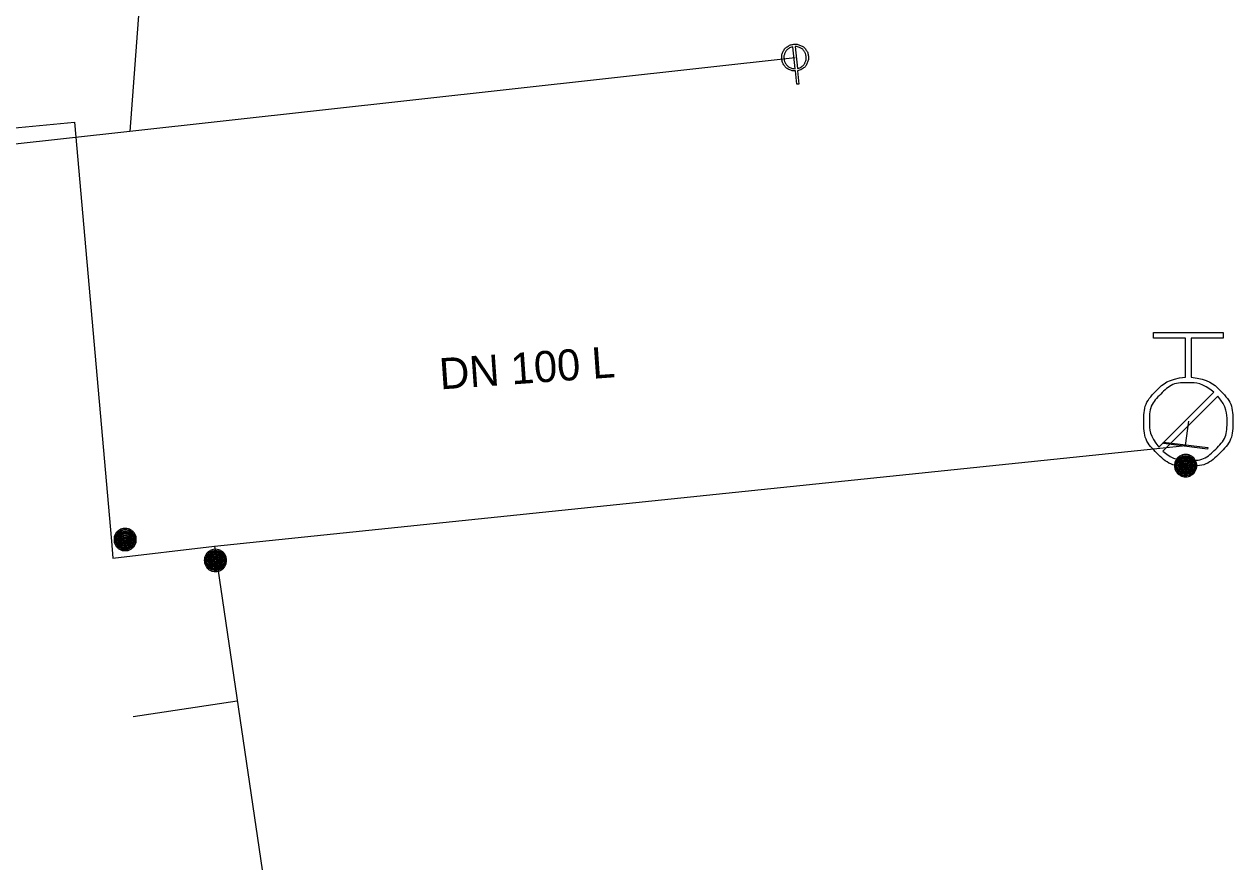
# Model space of a CAD drawing. Extents: x -818321 to -817653, y -1049725 to -1049329.
# Drawn here: x -817742.06 to -817714.89, y -1049399.87 to -1049380.87 of the extents above; entities that cross this region are included whole.
import ezdxf

# ---------------------------------------------------------------- set-up
doc = ezdxf.new("R2010")
doc.units = 0
doc.layers.add('Default', color=7, linetype='Continuous')
doc.layers.add('Level 0', color=7, linetype='Continuous')

msp = doc.modelspace()

# ---------------------------------------------------------------- linework, layer by layer
at = {"layer": 'Default'}
for points in [[(-817724.728, -1049381.869), (-817724.78, -1049381.375)], [(-817724.731, -1049381.37), (-817724.679, -1049381.864)], [(-817724.674, -1049381.915), (-817724.642, -1049382.214), (-817724.691, -1049382.219), (-817724.723, -1049381.92)], [(-817715.952, -1049388.805), (-817715.952, -1049387.926), (-817716.67, -1049387.926), (-817716.67, -1049387.801), (-817715.108, -1049387.801), (-817715.108, -1049387.926), (-817715.827, -1049387.926), (-817715.827, -1049388.805)], [(-817716.549, -1049390.374), (-817715.317, -1049389.139)], [(-817715.227, -1049389.229), (-817716.461, -1049390.464)], [(-817716.444, -1049390.263), (-817715.452, -1049390.385), (-817715.456, -1049390.416), (-817716.448, -1049390.294), (-817716.444, -1049390.263)]]:
    msp.add_lwpolyline(points, dxfattribs=at)
for points in [[(-817724.723, -1049381.92), (-817724.785, -1049381.923), (-817724.851, -1049381.894), (-817724.926, -1049381.863), (-817724.973, -1049381.796), (-817725.02, -1049381.729), (-817725.028, -1049381.651), (-817725.036, -1049381.573), (-817725.003, -1049381.497), (-817724.971, -1049381.421), (-817724.904, -1049381.375), (-817724.837, -1049381.329), (-817724.761, -1049381.321), (-817724.686, -1049381.314), (-817724.61, -1049381.345), (-817724.535, -1049381.375), (-817724.487, -1049381.443), (-817724.439, -1049381.51), (-817724.431, -1049381.588), (-817724.423, -1049381.666), (-817724.455, -1049381.741), (-817724.487, -1049381.816), (-817724.554, -1049381.863), (-817724.612, -1049381.904), (-817724.674, -1049381.915)], [(-817724.78, -1049381.375), (-817724.827, -1049381.384), (-817724.875, -1049381.417), (-817724.931, -1049381.455), (-817724.958, -1049381.518), (-817724.985, -1049381.581), (-817724.978, -1049381.646), (-817724.972, -1049381.711), (-817724.933, -1049381.766), (-817724.894, -1049381.821), (-817724.831, -1049381.848), (-817724.777, -1049381.871), (-817724.728, -1049381.869)], [(-817724.679, -1049381.864), (-817724.631, -1049381.856), (-817724.582, -1049381.822), (-817724.527, -1049381.783), (-817724.5, -1049381.721), (-817724.474, -1049381.658), (-817724.481, -1049381.594), (-817724.488, -1049381.529), (-817724.527, -1049381.473), (-817724.567, -1049381.417), (-817724.63, -1049381.391), (-817724.683, -1049381.369), (-817724.731, -1049381.37)], [(-817715.827, -1049388.805), (-817715.438, -1049388.835), (-817715.18, -1049389.094), (-817714.889, -1049389.387), (-817714.889, -1049389.803), (-817714.889, -1049390.217), (-817715.182, -1049390.509), (-817715.475, -1049390.801), (-817715.891, -1049390.801), (-817716.303, -1049390.801), (-817716.596, -1049390.509), (-817716.889, -1049390.217), (-817716.889, -1049389.803), (-817716.889, -1049389.387), (-817716.598, -1049389.094), (-817716.34, -1049388.833), (-817715.952, -1049388.805)], [(-817715.317, -1049389.139), (-817715.559, -1049388.926), (-817715.891, -1049388.926), (-817716.254, -1049388.926), (-817716.509, -1049389.181), (-817716.764, -1049389.436), (-817716.764, -1049389.8), (-817716.764, -1049390.132), (-817716.549, -1049390.374)], [(-817716.461, -1049390.464), (-817716.221, -1049390.673), (-817715.891, -1049390.676), (-817715.53, -1049390.673), (-817715.274, -1049390.418), (-817715.018, -1049390.163), (-817715.018, -1049389.8), (-817715.018, -1049389.469), (-817715.227, -1049389.229)], [(-817715.95, -1049390.54), (-817715.887, -1049390.54), (-817715.827, -1049390.572), (-817715.767, -1049390.605), (-817715.734, -1049390.665), (-817715.7, -1049390.725), (-817715.7, -1049390.79), (-817715.7, -1049390.855), (-817715.733, -1049390.915), (-817715.766, -1049390.974), (-817715.825, -1049391.007), (-817715.885, -1049391.04), (-817715.95, -1049391.04), (-817716.015, -1049391.04), (-817716.074, -1049391.007), (-817716.134, -1049390.974), (-817716.167, -1049390.915), (-817716.2, -1049390.855), (-817716.2, -1049390.79), (-817716.2, -1049390.725), (-817716.166, -1049390.665), (-817716.133, -1049390.605), (-817716.073, -1049390.572), (-817716.013, -1049390.54), (-817715.95, -1049390.54)], [(-817715.95, -1049390.564), (-817716.007, -1049390.564), (-817716.061, -1049390.593), (-817716.116, -1049390.622), (-817716.146, -1049390.677), (-817716.176, -1049390.731), (-817716.176, -1049390.79), (-817716.176, -1049390.849), (-817716.147, -1049390.903), (-817716.117, -1049390.957), (-817716.063, -1049390.987), (-817716.009, -1049391.017), (-817715.95, -1049391.017), (-817715.891, -1049391.017), (-817715.837, -1049390.987), (-817715.783, -1049390.957), (-817715.753, -1049390.903), (-817715.723, -1049390.849), (-817715.723, -1049390.79), (-817715.723, -1049390.731), (-817715.754, -1049390.677), (-817715.785, -1049390.622), (-817715.839, -1049390.593), (-817715.893, -1049390.564), (-817715.95, -1049390.564)], [(-817715.95, -1049390.581), (-817715.897, -1049390.581), (-817715.847, -1049390.608), (-817715.797, -1049390.635), (-817715.769, -1049390.685), (-817715.74, -1049390.736), (-817715.74, -1049390.79), (-817715.74, -1049390.845), (-817715.768, -1049390.895), (-817715.795, -1049390.944), (-817715.845, -1049390.972), (-817715.895, -1049391), (-817715.95, -1049391), (-817716.004, -1049391), (-817716.054, -1049390.972), (-817716.104, -1049390.944), (-817716.132, -1049390.895), (-817716.159, -1049390.845), (-817716.159, -1049390.79), (-817716.159, -1049390.736), (-817716.131, -1049390.685), (-817716.103, -1049390.635), (-817716.053, -1049390.608), (-817716.003, -1049390.581), (-817715.95, -1049390.581)], [(-817715.95, -1049390.603), (-817716.028, -1049390.603), (-817716.083, -1049390.658), (-817716.137, -1049390.713), (-817716.137, -1049390.79), (-817716.137, -1049390.868), (-817716.082, -1049390.923), (-817716.027, -1049390.978), (-817715.95, -1049390.978), (-817715.872, -1049390.978), (-817715.817, -1049390.923), (-817715.762, -1049390.868), (-817715.762, -1049390.79), (-817715.762, -1049390.713), (-817715.817, -1049390.658), (-817715.871, -1049390.603), (-817715.95, -1049390.603)], [(-817715.95, -1049390.626), (-817715.882, -1049390.626), (-817715.834, -1049390.674), (-817715.786, -1049390.722), (-817715.786, -1049390.79), (-817715.786, -1049390.858), (-817715.834, -1049390.906), (-817715.882, -1049390.954), (-817715.95, -1049390.954), (-817716.019, -1049390.954), (-817716.067, -1049390.906), (-817716.114, -1049390.858), (-817716.114, -1049390.79), (-817716.114, -1049390.722), (-817716.067, -1049390.674), (-817716.019, -1049390.626), (-817715.95, -1049390.626)], [(-817715.95, -1049390.645), (-817716.01, -1049390.645), (-817716.052, -1049390.688), (-817716.095, -1049390.73), (-817716.095, -1049390.79), (-817716.095, -1049390.85), (-817716.052, -1049390.892), (-817716.01, -1049390.934), (-817715.95, -1049390.934), (-817715.891, -1049390.934), (-817715.848, -1049390.892), (-817715.806, -1049390.85), (-817715.806, -1049390.79), (-817715.806, -1049390.73), (-817715.848, -1049390.688), (-817715.89, -1049390.645), (-817715.95, -1049390.645)], [(-817715.95, -1049390.665), (-817715.898, -1049390.665), (-817715.861, -1049390.702), (-817715.825, -1049390.738), (-817715.825, -1049390.79), (-817715.825, -1049390.842), (-817715.861, -1049390.879), (-817715.898, -1049390.915), (-817715.95, -1049390.915), (-817716.002, -1049390.915), (-817716.038, -1049390.879), (-817716.075, -1049390.842), (-817716.075, -1049390.79), (-817716.075, -1049390.738), (-817716.039, -1049390.702), (-817716.002, -1049390.665), (-817715.95, -1049390.665)], [(-817715.95, -1049390.688), (-817715.992, -1049390.688), (-817716.022, -1049390.718), (-817716.052, -1049390.748), (-817716.052, -1049390.79), (-817716.052, -1049390.832), (-817716.022, -1049390.862), (-817715.992, -1049390.892), (-817715.95, -1049390.892), (-817715.908, -1049390.892), (-817715.878, -1049390.862), (-817715.849, -1049390.832), (-817715.849, -1049390.79), (-817715.849, -1049390.748), (-817715.878, -1049390.718), (-817715.908, -1049390.688), (-817715.95, -1049390.688)], [(-817715.95, -1049390.706), (-817715.915, -1049390.706), (-817715.89, -1049390.73), (-817715.866, -1049390.755), (-817715.866, -1049390.79), (-817715.866, -1049390.825), (-817715.891, -1049390.85), (-817715.915, -1049390.874), (-817715.95, -1049390.874), (-817715.985, -1049390.874), (-817716.01, -1049390.85), (-817716.034, -1049390.825), (-817716.034, -1049390.79), (-817716.034, -1049390.755), (-817716.01, -1049390.73), (-817715.985, -1049390.706), (-817715.95, -1049390.706)], [(-817715.95, -1049390.728), (-817715.976, -1049390.728), (-817715.994, -1049390.746), (-817716.012, -1049390.764), (-817716.012, -1049390.79), (-817716.012, -1049390.816), (-817715.994, -1049390.834), (-817715.976, -1049390.853), (-817715.95, -1049390.853), (-817715.924, -1049390.853), (-817715.906, -1049390.834), (-817715.887, -1049390.816), (-817715.887, -1049390.79), (-817715.887, -1049390.764), (-817715.906, -1049390.746), (-817715.924, -1049390.728), (-817715.95, -1049390.728)], [(-817715.95, -1049390.751), (-817715.933, -1049390.751), (-817715.922, -1049390.762), (-817715.911, -1049390.774), (-817715.911, -1049390.79), (-817715.911, -1049390.806), (-817715.922, -1049390.818), (-817715.933, -1049390.829), (-817715.95, -1049390.829), (-817715.966, -1049390.829), (-817715.978, -1049390.818), (-817715.989, -1049390.806), (-817715.989, -1049390.79), (-817715.989, -1049390.774), (-817715.978, -1049390.762), (-817715.966, -1049390.751), (-817715.95, -1049390.751)], [(-817715.95, -1049390.767), (-817715.96, -1049390.767), (-817715.967, -1049390.773), (-817715.974, -1049390.78), (-817715.974, -1049390.79), (-817715.974, -1049390.8), (-817715.967, -1049390.807), (-817715.96, -1049390.814), (-817715.95, -1049390.814), (-817715.94, -1049390.814), (-817715.933, -1049390.807), (-817715.927, -1049390.8), (-817715.927, -1049390.79), (-817715.927, -1049390.78), (-817715.933, -1049390.773), (-817715.94, -1049390.767), (-817715.95, -1049390.767)], [(-817739.79, -1049392.2), (-817739.727, -1049392.2), (-817739.667, -1049392.232), (-817739.607, -1049392.265), (-817739.574, -1049392.325), (-817739.54, -1049392.385), (-817739.54, -1049392.45), (-817739.54, -1049392.515), (-817739.573, -1049392.575), (-817739.606, -1049392.634), (-817739.665, -1049392.667), (-817739.725, -1049392.7), (-817739.79, -1049392.7), (-817739.855, -1049392.7), (-817739.914, -1049392.667), (-817739.974, -1049392.634), (-817740.007, -1049392.575), (-817740.04, -1049392.515), (-817740.04, -1049392.45), (-817740.04, -1049392.385), (-817740.006, -1049392.325), (-817739.973, -1049392.265), (-817739.913, -1049392.232), (-817739.853, -1049392.2), (-817739.79, -1049392.2)], [(-817739.79, -1049392.224), (-817739.847, -1049392.224), (-817739.901, -1049392.253), (-817739.956, -1049392.282), (-817739.986, -1049392.337), (-817740.016, -1049392.391), (-817740.016, -1049392.45), (-817740.016, -1049392.509), (-817739.987, -1049392.563), (-817739.957, -1049392.617), (-817739.903, -1049392.647), (-817739.849, -1049392.677), (-817739.79, -1049392.677), (-817739.731, -1049392.677), (-817739.677, -1049392.647), (-817739.623, -1049392.617), (-817739.593, -1049392.563), (-817739.563, -1049392.509), (-817739.563, -1049392.45), (-817739.563, -1049392.391), (-817739.594, -1049392.337), (-817739.625, -1049392.282), (-817739.679, -1049392.253), (-817739.733, -1049392.224), (-817739.79, -1049392.224)], [(-817739.79, -1049392.241), (-817739.737, -1049392.241), (-817739.687, -1049392.268), (-817739.637, -1049392.295), (-817739.609, -1049392.345), (-817739.58, -1049392.396), (-817739.58, -1049392.45), (-817739.58, -1049392.505), (-817739.608, -1049392.555), (-817739.635, -1049392.604), (-817739.685, -1049392.632), (-817739.735, -1049392.66), (-817739.79, -1049392.66), (-817739.844, -1049392.66), (-817739.894, -1049392.632), (-817739.944, -1049392.604), (-817739.972, -1049392.555), (-817739.999, -1049392.505), (-817739.999, -1049392.45), (-817739.999, -1049392.396), (-817739.971, -1049392.345), (-817739.943, -1049392.295), (-817739.893, -1049392.268), (-817739.843, -1049392.241), (-817739.79, -1049392.241)], [(-817739.79, -1049392.263), (-817739.868, -1049392.263), (-817739.923, -1049392.318), (-817739.977, -1049392.373), (-817739.977, -1049392.45), (-817739.977, -1049392.528), (-817739.922, -1049392.583), (-817739.867, -1049392.638), (-817739.79, -1049392.638), (-817739.712, -1049392.638), (-817739.657, -1049392.583), (-817739.602, -1049392.528), (-817739.602, -1049392.45), (-817739.602, -1049392.373), (-817739.657, -1049392.318), (-817739.711, -1049392.263), (-817739.79, -1049392.263)], [(-817739.79, -1049392.286), (-817739.722, -1049392.286), (-817739.674, -1049392.334), (-817739.626, -1049392.382), (-817739.626, -1049392.45), (-817739.626, -1049392.518), (-817739.674, -1049392.566), (-817739.722, -1049392.614), (-817739.79, -1049392.614), (-817739.859, -1049392.614), (-817739.907, -1049392.566), (-817739.954, -1049392.518), (-817739.954, -1049392.45), (-817739.954, -1049392.382), (-817739.907, -1049392.334), (-817739.859, -1049392.286), (-817739.79, -1049392.286)], [(-817739.79, -1049392.305), (-817739.85, -1049392.305), (-817739.892, -1049392.348), (-817739.935, -1049392.39), (-817739.935, -1049392.45), (-817739.935, -1049392.51), (-817739.892, -1049392.552), (-817739.85, -1049392.594), (-817739.79, -1049392.594), (-817739.731, -1049392.594), (-817739.688, -1049392.552), (-817739.646, -1049392.51), (-817739.646, -1049392.45), (-817739.646, -1049392.39), (-817739.688, -1049392.348), (-817739.73, -1049392.305), (-817739.79, -1049392.305)], [(-817739.79, -1049392.325), (-817739.738, -1049392.325), (-817739.701, -1049392.362), (-817739.665, -1049392.398), (-817739.665, -1049392.45), (-817739.665, -1049392.502), (-817739.701, -1049392.539), (-817739.738, -1049392.575), (-817739.79, -1049392.575), (-817739.842, -1049392.575), (-817739.878, -1049392.539), (-817739.915, -1049392.502), (-817739.915, -1049392.45), (-817739.915, -1049392.398), (-817739.879, -1049392.362), (-817739.842, -1049392.325), (-817739.79, -1049392.325)], [(-817739.79, -1049392.348), (-817739.832, -1049392.348), (-817739.862, -1049392.378), (-817739.892, -1049392.408), (-817739.892, -1049392.45), (-817739.892, -1049392.492), (-817739.862, -1049392.522), (-817739.832, -1049392.552), (-817739.79, -1049392.552), (-817739.748, -1049392.552), (-817739.718, -1049392.522), (-817739.689, -1049392.492), (-817739.689, -1049392.45), (-817739.689, -1049392.408), (-817739.718, -1049392.378), (-817739.748, -1049392.348), (-817739.79, -1049392.348)], [(-817739.79, -1049392.366), (-817739.755, -1049392.366), (-817739.73, -1049392.39), (-817739.706, -1049392.415), (-817739.706, -1049392.45), (-817739.706, -1049392.485), (-817739.731, -1049392.51), (-817739.755, -1049392.534), (-817739.79, -1049392.534), (-817739.825, -1049392.534), (-817739.85, -1049392.51), (-817739.874, -1049392.485), (-817739.874, -1049392.45), (-817739.874, -1049392.415), (-817739.85, -1049392.39), (-817739.825, -1049392.366), (-817739.79, -1049392.366)], [(-817739.79, -1049392.388), (-817739.816, -1049392.388), (-817739.834, -1049392.406), (-817739.852, -1049392.424), (-817739.852, -1049392.45), (-817739.852, -1049392.476), (-817739.834, -1049392.494), (-817739.816, -1049392.513), (-817739.79, -1049392.513), (-817739.764, -1049392.513), (-817739.746, -1049392.494), (-817739.727, -1049392.476), (-817739.727, -1049392.45), (-817739.727, -1049392.424), (-817739.746, -1049392.406), (-817739.764, -1049392.388), (-817739.79, -1049392.388)], [(-817739.79, -1049392.411), (-817739.773, -1049392.411), (-817739.762, -1049392.422), (-817739.751, -1049392.434), (-817739.751, -1049392.45), (-817739.751, -1049392.466), (-817739.762, -1049392.478), (-817739.773, -1049392.489), (-817739.79, -1049392.489), (-817739.806, -1049392.489), (-817739.818, -1049392.478), (-817739.829, -1049392.466), (-817739.829, -1049392.45), (-817739.829, -1049392.434), (-817739.818, -1049392.422), (-817739.806, -1049392.411), (-817739.79, -1049392.411)], [(-817739.79, -1049392.427), (-817739.8, -1049392.427), (-817739.807, -1049392.433), (-817739.814, -1049392.44), (-817739.814, -1049392.45), (-817739.814, -1049392.46), (-817739.807, -1049392.467), (-817739.8, -1049392.474), (-817739.79, -1049392.474), (-817739.78, -1049392.474), (-817739.773, -1049392.467), (-817739.767, -1049392.46), (-817739.767, -1049392.45), (-817739.767, -1049392.44), (-817739.773, -1049392.433), (-817739.78, -1049392.427), (-817739.79, -1049392.427)], [(-817737.76, -1049392.67), (-817737.697, -1049392.67), (-817737.637, -1049392.702), (-817737.577, -1049392.735), (-817737.544, -1049392.795), (-817737.51, -1049392.855), (-817737.51, -1049392.92), (-817737.51, -1049392.985), (-817737.543, -1049393.045), (-817737.576, -1049393.104), (-817737.635, -1049393.137), (-817737.695, -1049393.17), (-817737.76, -1049393.17), (-817737.825, -1049393.17), (-817737.884, -1049393.137), (-817737.944, -1049393.104), (-817737.977, -1049393.045), (-817738.01, -1049392.985), (-817738.01, -1049392.92), (-817738.01, -1049392.855), (-817737.976, -1049392.795), (-817737.943, -1049392.735), (-817737.883, -1049392.702), (-817737.823, -1049392.67), (-817737.76, -1049392.67)], [(-817737.76, -1049392.694), (-817737.817, -1049392.694), (-817737.871, -1049392.723), (-817737.926, -1049392.752), (-817737.956, -1049392.807), (-817737.986, -1049392.861), (-817737.986, -1049392.92), (-817737.986, -1049392.979), (-817737.957, -1049393.033), (-817737.927, -1049393.087), (-817737.873, -1049393.117), (-817737.819, -1049393.147), (-817737.76, -1049393.147), (-817737.701, -1049393.147), (-817737.647, -1049393.117), (-817737.593, -1049393.087), (-817737.563, -1049393.033), (-817737.533, -1049392.979), (-817737.533, -1049392.92), (-817737.533, -1049392.861), (-817737.564, -1049392.807), (-817737.595, -1049392.752), (-817737.649, -1049392.723), (-817737.703, -1049392.694), (-817737.76, -1049392.694)], [(-817737.76, -1049392.711), (-817737.707, -1049392.711), (-817737.657, -1049392.738), (-817737.607, -1049392.765), (-817737.579, -1049392.815), (-817737.55, -1049392.866), (-817737.55, -1049392.92), (-817737.55, -1049392.975), (-817737.578, -1049393.025), (-817737.605, -1049393.074), (-817737.655, -1049393.102), (-817737.705, -1049393.13), (-817737.76, -1049393.13), (-817737.814, -1049393.13), (-817737.864, -1049393.102), (-817737.914, -1049393.074), (-817737.942, -1049393.025), (-817737.969, -1049392.975), (-817737.969, -1049392.92), (-817737.969, -1049392.866), (-817737.941, -1049392.815), (-817737.913, -1049392.765), (-817737.863, -1049392.738), (-817737.813, -1049392.711), (-817737.76, -1049392.711)], [(-817737.76, -1049392.733), (-817737.838, -1049392.733), (-817737.893, -1049392.788), (-817737.947, -1049392.843), (-817737.947, -1049392.92), (-817737.947, -1049392.998), (-817737.892, -1049393.053), (-817737.837, -1049393.108), (-817737.76, -1049393.108), (-817737.682, -1049393.108), (-817737.627, -1049393.053), (-817737.572, -1049392.998), (-817737.572, -1049392.92), (-817737.572, -1049392.843), (-817737.627, -1049392.788), (-817737.681, -1049392.733), (-817737.76, -1049392.733)], [(-817737.76, -1049392.756), (-817737.692, -1049392.756), (-817737.644, -1049392.804), (-817737.596, -1049392.852), (-817737.596, -1049392.92), (-817737.596, -1049392.988), (-817737.644, -1049393.036), (-817737.692, -1049393.084), (-817737.76, -1049393.084), (-817737.829, -1049393.084), (-817737.877, -1049393.036), (-817737.924, -1049392.988), (-817737.924, -1049392.92), (-817737.924, -1049392.852), (-817737.877, -1049392.804), (-817737.829, -1049392.756), (-817737.76, -1049392.756)], [(-817737.76, -1049392.775), (-817737.82, -1049392.775), (-817737.862, -1049392.818), (-817737.905, -1049392.86), (-817737.905, -1049392.92), (-817737.905, -1049392.98), (-817737.862, -1049393.022), (-817737.82, -1049393.064), (-817737.76, -1049393.064), (-817737.701, -1049393.064), (-817737.658, -1049393.022), (-817737.616, -1049392.98), (-817737.616, -1049392.92), (-817737.616, -1049392.86), (-817737.658, -1049392.818), (-817737.7, -1049392.775), (-817737.76, -1049392.775)], [(-817737.76, -1049392.795), (-817737.708, -1049392.795), (-817737.671, -1049392.832), (-817737.635, -1049392.868), (-817737.635, -1049392.92), (-817737.635, -1049392.972), (-817737.671, -1049393.009), (-817737.708, -1049393.045), (-817737.76, -1049393.045), (-817737.812, -1049393.045), (-817737.848, -1049393.009), (-817737.885, -1049392.972), (-817737.885, -1049392.92), (-817737.885, -1049392.868), (-817737.849, -1049392.832), (-817737.812, -1049392.795), (-817737.76, -1049392.795)], [(-817737.76, -1049392.818), (-817737.802, -1049392.818), (-817737.832, -1049392.848), (-817737.862, -1049392.878), (-817737.862, -1049392.92), (-817737.862, -1049392.962), (-817737.832, -1049392.992), (-817737.802, -1049393.022), (-817737.76, -1049393.022), (-817737.718, -1049393.022), (-817737.688, -1049392.992), (-817737.659, -1049392.962), (-817737.659, -1049392.92), (-817737.659, -1049392.878), (-817737.688, -1049392.848), (-817737.718, -1049392.818), (-817737.76, -1049392.818)], [(-817737.76, -1049392.836), (-817737.725, -1049392.836), (-817737.7, -1049392.86), (-817737.676, -1049392.885), (-817737.676, -1049392.92), (-817737.676, -1049392.955), (-817737.701, -1049392.98), (-817737.725, -1049393.004), (-817737.76, -1049393.004), (-817737.795, -1049393.004), (-817737.82, -1049392.98), (-817737.844, -1049392.955), (-817737.844, -1049392.92), (-817737.844, -1049392.885), (-817737.82, -1049392.86), (-817737.795, -1049392.836), (-817737.76, -1049392.836)], [(-817737.76, -1049392.858), (-817737.786, -1049392.858), (-817737.804, -1049392.876), (-817737.822, -1049392.894), (-817737.822, -1049392.92), (-817737.822, -1049392.946), (-817737.804, -1049392.964), (-817737.786, -1049392.983), (-817737.76, -1049392.983), (-817737.734, -1049392.983), (-817737.716, -1049392.964), (-817737.697, -1049392.946), (-817737.697, -1049392.92), (-817737.697, -1049392.894), (-817737.716, -1049392.876), (-817737.734, -1049392.858), (-817737.76, -1049392.858)], [(-817737.76, -1049392.881), (-817737.743, -1049392.881), (-817737.732, -1049392.892), (-817737.721, -1049392.904), (-817737.721, -1049392.92), (-817737.721, -1049392.936), (-817737.732, -1049392.948), (-817737.743, -1049392.959), (-817737.76, -1049392.959), (-817737.776, -1049392.959), (-817737.788, -1049392.948), (-817737.799, -1049392.936), (-817737.799, -1049392.92), (-817737.799, -1049392.904), (-817737.788, -1049392.892), (-817737.776, -1049392.881), (-817737.76, -1049392.881)], [(-817737.76, -1049392.897), (-817737.77, -1049392.897), (-817737.777, -1049392.903), (-817737.784, -1049392.91), (-817737.784, -1049392.92), (-817737.784, -1049392.93), (-817737.777, -1049392.937), (-817737.77, -1049392.944), (-817737.76, -1049392.944), (-817737.75, -1049392.944), (-817737.743, -1049392.937), (-817737.737, -1049392.93), (-817737.737, -1049392.92), (-817737.737, -1049392.91), (-817737.743, -1049392.903), (-817737.75, -1049392.897), (-817737.76, -1049392.897)]]:
    msp.add_open_spline(points, degree=3, dxfattribs=at)
at = {"layer": 'Level 0'}
for p, q in [((-817738.325, -1049364.887), (-817739.683, -1049383.281)), ((-817724.729, -1049381.625), (-817739.683, -1049383.281)), ((-817792.8, -1049388.031), (-817740.932, -1049383.074)), ((-817740.932, -1049383.074), (-817740.1, -1049392.488)), ((-817739.683, -1049383.281), (-817742.466, -1049383.589)), ((-817715.95, -1049390.34), (-817715.88, -1049389.79)), ((-817737.781, -1049392.602), (-817716.017, -1049390.345)), ((-817716.017, -1049390.345), (-817715.95, -1049390.34)), ((-817740.1, -1049392.488), (-817740.066, -1049392.872)), ((-817740.066, -1049392.872), (-817737.781, -1049392.602)), ((-817737.781, -1049392.602), (-817736.711, -1049399.873)), ((-817739.609, -1049396.425), (-817737.271, -1049396.072)), ((-817739.609, -1049396.425), (-817737.271, -1049396.072)), ((-817739.609, -1049396.425), (-817737.271, -1049396.072)), ((-817739.609, -1049396.425), (-817737.271, -1049396.072)), ((-817739.609, -1049396.425), (-817737.271, -1049396.072)), ((-817739.609, -1049396.425), (-817737.271, -1049396.072)), ((-817739.609, -1049396.425), (-817737.271, -1049396.072))]:
    msp.add_line(p, q, dxfattribs=at)

# ---------------------------------------------------------------- texts
msp.add_text('DN 100 L', height=0.7, rotation=4, dxfattribs=at).set_placement((-817732.704, -1049389.078))

doc.saveas('drawing.dxf')
